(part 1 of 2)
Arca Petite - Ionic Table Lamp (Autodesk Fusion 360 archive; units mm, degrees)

design "Marble Base - Ionic Table Lamp - 120V" references "Trove - TL", "Balon v2", "Marble Base - Silicone Gasket", "Rubber Grommet", "Marble Base - Plastic Insert", "Chinois", "Neoprene Pad", "2-Pole Plug End", "Arca Tall", "T9 - Bulb", "Facet Petite", "T9-5In"
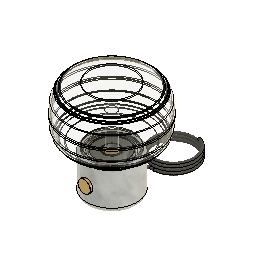
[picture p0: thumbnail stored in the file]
sketch "Sketch1" plane through (0, 0, 0) normal (0, 0, 1) x axis (1, 0, 0)
  circle C1 centre (0, 0) radius 63.5
  point P1 (0, 0)
  point P2 (0, 0)
  coincident P1 P2
extrude "Extrude1" new body sketch "Sketch1" along normal blind 101.6 bodies "Marble Base"
sketch "Sketch2" plane through (0, 0, 101.6) normal (0, 0, 1) x axis (-1, 0, 0)
  circle C1 centre (0, 0) radius 63.5
  circle C2 centre (0, 0) radius 53.975
  concentric C1 C2
  dimension "d3" diameter C2 = 107.95
extrude "Extrude2" cut sketch "Sketch2" profile of C2 against normal blind 34.925
sketch "Sketch3" plane through (0, 0, 66.675) normal (0, 0, 1) x axis (-1, 0, 0)
  circle C1 centre (0, 0) radius 53.975
  circle C2 centre (0, 0) radius 49.276
  point P1 (0, 0)
  point P3 (0, 0)
  coincident P1 P3
  dimension "d6" diameter C2 = 98.552
extrude "Extrude3" cut sketch "Sketch3" profile of C2 against normal blind 45.72
sketch "Sketch4" plane through (0, 0, 0) normal (0, 1, 0) x axis (1, 0, 0)
  circle C1 centre (0, -50.8) radius 3.81
  dimension "d9" diameter C1 = 7.62
extrude "Extrude4" cut sketch "Sketch4" against normal blind 127
sketch "Sketch5" plane through (0, 0, 0) normal (0, 1, 0) x axis (1, 0, 0)
  line L1 (0, -25.4) -> (0, 0)
  line L2 (0, -30.48) -> (0, -25.4)
  circle C1 centre (0, -30.48) radius 5.08
  point P1 (0, 0)
  point P2 (0, 0)
  point P4 (0, -30.48)
  point P5 (0, -30.48)
  coincident P1 P2
  vertical L1
  parallel L1 L2
  coincident P4 P5
  dimension "d12" diameter C1 = 10.16
extrude "Extrude5" cut sketch "Sketch5" profile of C1 along normal blind 114.3
fillet "Fillet1" radius 6.35 3.175 4.064
derived_base_feature "Derived Base Feature1" bodies "Rotary Switch"
derived_base_feature "Derived Base Feature1" bodies "Coiled - SVT (Blk Fabric)"
derived_base_feature "Derived Base Feature1" bodies "Glass Globe"
derived_base_feature "Derived Base Feature1" bodies "Metal Housing"
derived_base_feature "Derived Base Feature1" bodies "Metal Socket Cover"
derived_base_feature "Derived Base Feature1" bodies "Porcelain Socket"
derived_base_feature "Derived Base Feature1" bodies "Brass Dial - Dimmer Knob"
component_from_bodies "Body->Comp1"
offset_faces "OffsetFaces1" distance 12.7
offset_faces "OffsetFaces2" distance -12.7
derived_base_feature "Derived Base Feature1" bodies "Solitaire Petite"
move "Move1"
offset_faces "OffsetFaces1" distance 20.32
move "Move2"
extrude "Extrude6" add of existing geometry blind 25.4
offset_faces "OffsetFaces2" distance -3.81
fillet "Fillet2" radius 2.54
move "Move3"
derived_base_feature "Derived Base Feature2" bodies "Facet Petite"
move "Move4"
offset_faces "OffsetFaces1" distance 2.54
move "Move1"
derived_base_feature "Derived Base Feature1" bodies "Body1"
derived_base_feature "Derived Base Feature1" bodies "Body1"
derived_base_feature "Derived Base Feature1" bodies "Body1"
derived_base_feature "Derived Base Feature1" bodies "Body1"
derived_base_feature "Derived Base Feature1" bodies "Body1"
derived_base_feature "Derived Base Feature1" bodies "Body1", "Body2"
derived_base_feature "Derived Base Feature1" bodies "Body1"
position "Position1"
external_derived "ExternalDerived5" bodies "Plastic Insert"
derived_instance "DerivedInstance15"
offset_faces "OffsetFaces1" distance 3.81
offset_faces "OffsetFaces2" distance -1.0414
move "Move6"
external_derived "ExternalDerived6" sketch "Sketch3" bodies "Silicone Gasket"
derived_instance "DerivedInstance16"
offset_faces "OffsetFaces3" distance -10.795
move "Move1"
move_face "MoveFace1"
position "Position2"
position "Position3"
position "Position4"
position "Position5"
move "Move2"
position "Position6"
offset_faces "OffsetFaces2" distance -7.62
chamfer "Chamfer1" distance 0.381
remove_instance "RemoveInstance1"
remove_instance "RemoveInstance2"
remove_instance "RemoveInstance3"
remove_instance "RemoveInstance4"
move "Move1"
derived_base_feature "Derived Base Feature5" bodies "Oculo Petite"
align "Align1"
external_derived "ExternalDerived8"
derived_base_feature "Derived Base Feature7" bodies "Balon v2"
derived_base_feature "Derived Base Feature8" bodies "Balon v3"
align "Align3"
align "Align4"
external_derived "ExternalDerived10"
component_insert "Component Insert1"
position "Position7"
position "Position8"
derived_base_feature "Derived Base Feature11" bodies "Trove - TL"
move "Move10"
move "Move11"
remove_instance "RemoveInstance5"
split "Split1" bodies "Trove - TL (1)"
remove_body "RemoveBody2"
remove_body "RemoveBody3"
external_derived "ExternalDerived13" bodies "Trove - TL"
derived_instance "DerivedInstance20"
remove_body "RemoveBody4"
remove_body "RemoveBody5"
component_insert "Component Insert2"
component_insert "Component Insert3"
component_from_bodies "Body->Comp2"
remove_body "RemoveBody7"
move "Move12"
move "Move13"
sketch "Sketch6" plane through (0, 0, 97.917) normal (0, 0, 1) x axis (-1, 0, 0)
  circle C1 centre (0, 0) radius 41.275
  circle C2 centre (0, 0) radius 19.685
  arc A1 centre (0, 0) radius 29.3982 clockwise from (-27.6283, 10.0466) to (27.6283, 10.0466)
  arc A2 centre (0, 0) radius 26.2232 clockwise from (-24.6444, 8.9616) to (24.6444, 8.9616)
  arc A3 centre (0, 0) radius 32.5732 clockwise from (-30.6121, 11.1317) to (30.6121, 11.1317)
  arc A4 centre (0, 0) radius 35.7482 clockwise from (-33.596, 12.2167) to (33.596, 12.2167)
  point P1 (0, 0)
  point P3 (0, 0)
  coincident P1 P3
  dimension "d37" = -3.175
  dimension "d38" = 3.175
  dimension "d39" = 6.35
  dimension "d40" Text1-Height = 2.54
  dimension "d41" Text2-Height = 2.54
  dimension "d42" Text3-Height = 2.54
  dimension "d43" Text4-Height = 2.54
extrude "Extrude1" cut sketch "Sketch6" against normal blind 0.254
external_derived "ExternalDerived14" bodies "Rubber Grommet"
derived_instance "DerivedInstance19"
external_derived "ExternalDerived15" bodies "2-Pole Plug End"
derived_instance "DerivedInstance18"
external_derived "ExternalDerived16" bodies "Neoprene Pad"
derived_instance "DerivedInstance17"
position "Position9"
position "Position10"
position "Position11"
position "Position12"
external_derived "ExternalDerived17" bodies "Chinois"
derived_instance "DerivedInstance21"
position "Position13"
move "Move3"
remove_body "RemoveBody8"
component_insert "Component Insert4"
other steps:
derived_base_feature "Derived Base Feature1" bodies "Trove - TL"
derived_base_feature "Derived Base Feature1" bodies "Chinois"
derived_base_feature "Derived Base Feature1" bodies "Rubber Grommet"
derived_base_feature "Derived Base Feature1" bodies "2-Pole Plug End"
derived_base_feature "Derived Base Feature1" bodies "Neoprene Pad"
move "Move1"
base_feature "Base Feature1" bodies "Oculo Petite", "Arca Petite"
derived_base_feature "Derived Base Feature1" bodies "Plastic Insert"
derived_base_feature "Derived Base Feature1" bodies "Silicone Gasket"
base_feature "Base Feature1" bodies "Marble Base"
move "Move8"
derived_base_feature "Derived Base Feature"
create_component "CreateComponent1"
create_component "CreateComponent2"
create_component "CreateComponent3"
create_component "CreateComponent4"
create_component "CreateComponent5"
create_component "CreateComponent6"
create_component "CreateComponent7"
create_component "CreateComponent8"
remove_body "RemoveBody1"
create_component "CreateComponent9"
create_component "CreateComponent10"
create_component "CreateComponent11"
create_component "CreateComponent12"
create_component "CreateComponent13"
create_component "CreateComponent14"
create_component "CreateComponent15"
create_component "CreateComponent16"
create_component "CreateComponent17"
create_component "CreateComponent18"
remove_body "RemoveBody6"
create_component "CreateComponent19"
create_component "CreateComponent20"
create_component "CreateComponent21"
create_component "CreateComponent22"
create_component "CreateComponent23"
named bodies: "Marble Base", "Rotary Switch", "Coiled - SVT (Blk Fabric)", "Glass Globe", "Metal Housing", "Metal Socket Cover", "Porcelain Socket", "Brass Dial - Dimmer Knob", "Solitaire Petite", "Facet Petite", "Body1", "Body2", "Plastic Insert", "Silicone Gasket", "Oculo Petite", "Balon v2", "Balon v3", "Trove - TL", "Trove - TL (1)", "Arca Petite", "Neoprene Pad", "2-Pole Plug End", "Rubber Grommet", "Chinois"

design "Neoprene Pad"
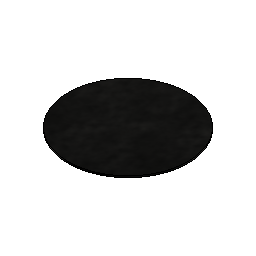
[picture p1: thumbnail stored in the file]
sketch "Sketch1" plane through (0, 0, 0) normal (0, 0, 1) x axis (1, 0, 0)
  circle C1 centre (0, 0) radius 57.15
  point P1 (0, 0)
  point P2 (0, 0)
  coincident P1 P2
extrude "Extrude1" new body sketch "Sketch1" along normal blind 1.5875 bodies "Neoprene Pad"
component_from_bodies "Body->Comp"
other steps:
base_feature "Base Feature" bodies "Neoprene Pad"
create_component "CreateComponent1"
remove_body "RemoveBody1"
named bodies: "Neoprene Pad"

design "T9 - Bulb"
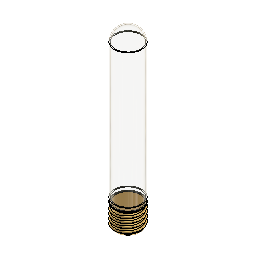
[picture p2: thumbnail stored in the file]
sketch "Sketch1" plane through (0, 0, 0) normal (0, 1, 0) x axis (1, 0, 0)
  line L1 (0, -166.37) -> (0, 0)
  line L2 (13.97, -13.97) -> (13.97, -152.4)
  line L3 (-13.97, -152.4) -> (-13.97, -13.97)
  line L4 (0, 0) -> (0, -166.37)
  line L5 (12.97, -13.97) -> (12.97, -152.4)
  line L6 (-12.97, -152.4) -> (-12.97, -13.97)
  line L7 (-12.3978, -10.16) -> (-13.4404, -10.16)
  line L8 (13.4404, -10.16) -> (12.3978, -10.16)
  arc A1 centre (0, -152.4) radius 13.97 clockwise from (13.97, -152.4) to (-13.97, -152.4)
  arc A2 centre (0, -152.4) radius 12.97 clockwise from (12.97, -152.4) to (-12.97, -152.4)
  arc A3 centre (0, -13.97) radius 13.97 clockwise from (13.4404, -10.16) to (13.97, -13.97)
  arc A4 centre (0, -13.97) radius 13.97 clockwise from (-13.97, -13.97) to (-13.4404, -10.16)
  arc A5 centre (0, -13.97) radius 12.97 clockwise from (12.3978, -10.16) to (12.97, -13.97)
  arc A6 centre (0, -13.97) radius 12.97 clockwise from (-12.97, -13.97) to (-12.3978, -10.16)
  point P1 (0, 0)
  point P2 (0, 0)
  point P3 (0, -166.37)
  point P10 (0, 0)
  point P17 (13.4404, -10.16)
  point P19 (12.3978, -10.16)
  point P4 (13.97, -152.4)
  point P5 (13.97, -13.97)
  coincident P1 P2
  vertical L1
  tangent L2 A3
  tangent L3 A3
  parallel L2 L3
  tangent L3 A1
  tangent L2 A1
  midpoint P3 A1
  coincident P1 P10
  perpendicular L1 L7
  coincident P17 L7
  concentric A3 A4
  coincident P10 A3
  concentric A1 A2
  tangent L5 A2
  tangent L5 A5
  tangent L6 A5
  tangent L6 A2
  coincident P19 L7
  concentric A5 A6
  collinear L7 L8
  dimension "d6" distance L2 L3 = 27.94
  dimension "d7" distance P4 P5 = 138.43
revolve "Revolve1" sketch "Sketch1" AlongAngle 360 bodies "T9"
derived_base_feature "Derived Base Feature" bodies "E26 Base"
align "Align1"
move "Move1"
component_from_bodies "Body->Comp1"
component_from_bodies "Body->Comp2"
copy_paste "CutPaste1"
copy_paste "CutPaste2"
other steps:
base_feature "Base Feature1" bodies "T9"
base_feature "Base Feature1" bodies "E26 Base"
create_component "CreateComponent1"
create_component "CreateComponent2"
remove_body "RemoveBody1"
create_component "CreateComponent3"
remove_body "RemoveBody2"
remove_instance "RemoveInstance1"
remove_instance "RemoveInstance2"
named bodies: "T9", "E26 Base"

design "Marble Base - Silicone Gasket"
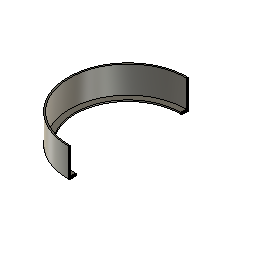
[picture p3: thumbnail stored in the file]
sketch "Sketch1" plane through (0, 0, 0) normal (0, 0, 1) x axis (1, 0, 0)
  circle C1 centre (0, 0) radius 53.34
  point P1 (0, 0)
  point P2 (0, 0)
  coincident P1 P2
extrude "Extrude1" new body sketch "Sketch1" along normal blind 25.4 bodies "Silicone Gasket"
shell "Shell1" innerThickness 1.27
sketch "Sketch2" plane through (0, 0, 1.27) normal (0, 0, 1) x axis (-1, 0, 0)
  circle C1 centre (0, 0) radius 52.07
  circle C2 centre (0, 0) radius 46.99
  concentric C1 C2
extrude "Extrude2" cut sketch "Sketch2" profile of C2 against normal blind 12.7
component_from_bodies "Body->Comp"
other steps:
base_feature "Base Feature" bodies "Silicone Gasket"
create_component "CreateComponent1"
remove_body "RemoveBody1"
named bodies: "Silicone Gasket"

design "2-Pole Plug End"
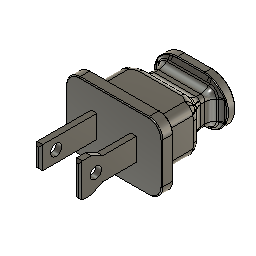
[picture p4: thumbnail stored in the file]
sketch "Sketch1" plane through (0, 0, 0) normal (0, 1, 0) x axis (1, 0, 0)
  line L1 (9.6837, 9.525) -> (-9.6837, 9.525)
  line L2 (13.4938, -5.715) -> (13.4938, 5.715)
  line L3 (-9.6837, -9.525) -> (9.6837, -9.525)
  line L4 (-13.4937, 5.715) -> (-13.4937, -5.715)
  line L5 (13.4938, -9.525) -> (-13.4937, 9.525)
  line L6 (-13.4937, -9.525) -> (13.4938, 9.525)
  arc A1 centre (-9.6837, -5.715) radius 3.81 clockwise from (-9.6837, -9.525) to (-13.4937, -5.715)
  arc A2 centre (9.6837, -5.715) radius 3.81 clockwise from (13.4938, -5.715) to (9.6837, -9.525)
  arc A3 centre (9.6837, 5.715) radius 3.81 clockwise from (9.6837, 9.525) to (13.4938, 5.715)
  arc A4 centre (-9.6837, 5.715) radius 3.81 clockwise from (-13.4937, 5.715) to (-9.6837, 9.525)
  point P6 (0, 0)
  point P1 (0, 0)
  point P5 (-13.4937, -9.525)
  point P4 (13.4938, -9.525)
  point P3 (13.4938, 9.525)
  point P2 (-13.4937, 9.525)
  horizontal L1
  perpendicular L1 L2
  parallel L1 L3
  parallel L2 L4
  coincident L5 P6
  coincident L6 P6
  coincident P1 P6
  coincident P5 L4
  coincident P5 L3
  tangent L4 A1
  tangent L3 A1
  coincident P4 L3
  coincident P4 L2
  tangent L3 A2
  tangent L2 A2
  equal A1 A2
  coincident P3 L2
  coincident P3 L1
  tangent L2 A3
  tangent L1 A3
  equal A1 A3
  coincident P2 L1
  coincident P2 L4
  tangent L1 A4
  tangent L4 A4
  equal A1 A4
  dimension "d1" distance P4 P5 = 26.9875
  dimension "d2" distance P2 P5 = 19.05
  dimension "d3" radius A1 = 3.81
extrude "Extrude1" new body sketch "Sketch1" profile of L1 L2 L3 L4 A1 A2 A3 A4 along normal blind 3.175
sketch "Sketch2" plane through (0, 3.175, 0) normal (0, 1, 0) x axis (-1, 0, 0)
  line L1 (9.6837, -9.525) -> (-9.6837, -9.525)
  line L2 (13.4937, 5.715) -> (13.4937, -5.715)
  line L3 (-9.6837, 9.525) -> (9.6837, 9.525)
  line L4 (-13.4938, -5.715) -> (-13.4938, 5.715)
  line L5 (10.16, -6.35) -> (-10.16, -6.35)
  line L6 (10.16, 6.35) -> (10.16, -6.35)
  line L7 (-10.16, 6.35) -> (10.16, 6.35)
  line L8 (-10.16, -6.35) -> (-10.16, 6.35)
  line L9 (10.16, 6.35) -> (-10.16, -6.35)
  line L10 (-10.16, 6.35) -> (10.16, -6.35)
  arc A1 centre (-9.6837, -5.715) radius 3.81 clockwise from (-9.6837, -9.525) to (-13.4938, -5.715)
  arc A2 centre (9.6837, -5.715) radius 3.81 clockwise from (13.4937, -5.715) to (9.6837, -9.525)
  arc A3 centre (9.6837, 5.715) radius 3.81 clockwise from (9.6837, 9.525) to (13.4937, 5.715)
  arc A4 centre (-9.6837, 5.715) radius 3.81 clockwise from (-13.4938, 5.715) to (-9.6837, 9.525)
  point P18 (0, 0)
  point P1 (0, 0)
  horizontal L5
  perpendicular L5 L6
  parallel L5 L7
  parallel L6 L8
  coincident L9 P18
  coincident L10 P18
  coincident P1 P18
extrude "Extrude2" add sketch "Sketch2" profile of L5 L6 L7 L8 along normal blind 9.525
sketch "Sketch3" plane through (0, 12.7, 0) normal (0, 1, 0) x axis (-1, 0, 0)
  line L1 (-10.16, -6.35) -> (-10.16, 6.35)
  line L2 (10.16, -6.35) -> (-10.16, -6.35)
  line L3 (10.16, 6.35) -> (10.16, -6.35)
  line L4 (-10.16, 6.35) -> (10.16, 6.35)
  line L5 (-7.1437, 3.9688) -> (7.1437, 3.9688)
  line L6 (-7.1437, -3.9688) -> (-7.1437, 3.9688)
  line L7 (7.1437, -3.9688) -> (-7.1437, -3.9688)
  line L8 (7.1437, 3.9688) -> (7.1437, -3.9688)
  line L9 (-7.1437, -3.9688) -> (7.1437, 3.9688)
  line L10 (7.1437, -3.9688) -> (-7.1437, 3.9688)
  point P10 (0, 0)
  point P1 (0, 0)
  point P8 (-7.1437, -3.9688)
  point P9 (7.1437, -3.9688)
  point P7 (-7.1437, 3.9688)
  horizontal L5
  perpendicular L5 L6
  parallel L5 L7
  parallel L6 L8
  coincident L9 P10
  coincident L10 P10
  coincident P1 P10
  dimension "d8" distance P8 P9 = 14.2875
  dimension "d9" distance P7 P8 = 7.9375
extrude "Extrude3" add sketch "Sketch3" profile of L5 L6 L7 L8 along normal blind 11.1125
fillet "Fillet1" radius 2.286 1.27 0.254
chamfer "Chamfer1" distance 3.429
fillet "Fillet2" radius 2.54 1.905
sketch "Sketch4" plane through (0, 23.8125, 0) normal (0, 1, 0) x axis (-1, 0, 0)
  line L1 (-7.1437, -2.6987) -> (-7.1437, 2.6987)
  line L2 (5.8737, -3.9688) -> (-5.8737, -3.9688)
  line L3 (7.1437, 2.6987) -> (7.1437, -2.6987)
  line L4 (-5.8737, 3.9688) -> (5.8737, 3.9688)
  line L5 (-3.81, 6.604) -> (3.81, 6.604)
  line L6 (3.81, -6.604) -> (-3.81, -6.604)
  line L7 (-10.414, 0) -> (10.414, 0)
  arc A1 centre (-5.8737, 2.6987) radius 1.27 clockwise from (-7.1437, 2.6987) to (-5.8737, 3.9688)
  arc A2 centre (-5.8737, -2.6987) radius 1.27 clockwise from (-5.8737, -3.9688) to (-7.1437, -2.6987)
  arc A3 centre (5.8737, -2.6987) radius 1.27 clockwise from (7.1437, -2.6987) to (5.8737, -3.9688)
  arc A4 centre (5.8737, 2.6987) radius 1.27 clockwise from (5.8737, 3.9688) to (7.1437, 2.6987)
  arc A5 centre (-3.81, 0) radius 6.604 clockwise from (-3.81, -6.604) to (-3.81, 6.604)
  arc A6 centre (3.81, 0) radius 6.604 clockwise from (3.81, 6.604) to (3.81, -6.604)
  point P20 (10.414, 0)
  point P21 (-10.414, 0)
  tangent L5 A5
  tangent A5 L6
  parallel L5 L6
  tangent L6 A6
  tangent L5 A6
  midpoint A6 P20
  midpoint A5 P21
  perpendicular L1 L7
extrude "Extrude4" add sketch "Sketch4" profile of A1 L1 A2 L2 A3 L3 A4 L4 L5 A5 L6 A6 against normal blind 2.286
chamfer "Chamfer2" distance 1.778
fillet "Fillet3" radius 1.778
fillet "Fillet4" radius 0.254
fillet "Fillet5" radius 0.254
fillet "Fillet6" radius 0.254
fillet "Fillet7" radius 3.175
sketch "Sketch5" plane through (0, 0, 0) normal (0, -1, 0) x axis (1, 0, 0)
  line L1 (-13.2397, -5.715) -> (-13.2397, 5.715)
  line L2 (9.6837, -9.271) -> (-9.6837, -9.271)
  line L3 (13.2397, 5.715) -> (13.2397, -5.715)
  line L4 (-9.6837, 9.271) -> (9.6837, 9.271)
  line L5 (-6.35, -3.175) -> (-6.35, 3.175)
  line L6 (6.35, 3.175) -> (-6.35, -3.175)
  line L7 (-6.35, 3.175) -> (6.35, -3.175)
  line L8 (-4.7625, 3.175) -> (-6.35, 3.175)
  line L9 (-4.7625, -3.175) -> (-4.7625, 3.175)
  line L10 (-6.35, -3.175) -> (-4.7625, -3.175)
  line L11 (-6.35, 3.175) -> (-6.35, -3.175)
  line L12 (0, -3.302) -> (0, 3.81)
  line L13 (4.7625, -3.175) -> (4.7625, 3.175)
  line L14 (4.7625, 3.175) -> (6.35, 3.175)
  line L15 (6.35, -3.175) -> (6.35, 3.175)
  line L16 (6.35, -3.175) -> (4.7625, -3.175)
  arc A1 centre (-9.6837, 5.715) radius 3.556 clockwise from (-13.2397, 5.715) to (-9.6837, 9.271)
  arc A2 centre (-9.6837, -5.715) radius 3.556 clockwise from (-9.6837, -9.271) to (-13.2397, -5.715)
  arc A3 centre (9.6837, -5.715) radius 3.556 clockwise from (13.2397, -5.715) to (9.6837, -9.271)
  arc A4 centre (9.6837, 5.715) radius 3.556 clockwise from (9.6837, 9.271) to (13.2397, 5.715)
  point P18 (0, 0)
  point P1 (0, 0)
  point P14 (-6.35, -3.175)
  point P27 (6.35, -3.175)
  point P17 (-6.35, 3.175)
  point P26 (6.35, 3.175)
  point P19 (-4.7625, 3.175)
  point P24 (4.7625, 3.175)
  point P20 (-4.7625, -3.175)
  point P25 (4.7625, -3.175)
  point P21 (-6.35, -3.175)
  point P28 (6.35, -3.175)
  point P15 (6.35, -3.175)
  point P16 (6.35, 3.175)
  coincident L6 P18
  coincident L7 P18
  coincident P1 P18
  horizontal L8
  vertical L9
  horizontal L10
  vertical L11
  vertical L12
  symmetric P14 L12 P27
  symmetric P17 L12 P26
  symmetric P19 L12 P24
  symmetric P20 L12 P25
  symmetric P21 L12 P28
  dimension "d36" distance P15 P16 = 6.35
  dimension "d37" distance P17 P19 = 1.5875
extrude "Extrude5" add sketch "Sketch5" profile of L5 L8 L9 L10 L11 L13 L14 L15 L16 along normal blind 15.875
sketch "Sketch7" plane through (0, 0, 3.175) normal (0, 0, 1) x axis (-1, 0, 0)
  line L1 (-4.7625, 0) -> (-6.35, 0)
  line L2 (-4.7625, 15.875) -> (-4.7625, 0)
  line L3 (-6.35, 15.875) -> (-4.7625, 15.875)
  line L4 (-6.35, 0) -> (-6.35, 15.875)
  line L5 (-4.7625, 15.875) -> (-6.35, 15.875)
  line L6 (-4.7625, 9.525) -> (-4.7625, 15.875)
  line L7 (-6.35, 9.525) -> (-4.7625, 9.525)
  line L8 (-6.35, 15.875) -> (-6.35, 9.525)
  point P5 (-6.35, 15.875)
  point P6 (-6.35, 15.875)
  point P9 (-6.35, 9.525)
  horizontal L5
  vertical L6
  horizontal L7
  vertical L8
  coincident P5 P6
  dimension "d45" distance P6 P9 = 6.35
extrude "Extrude7" add sketch "Sketch7" profile of L2 L3 L4 L5 L6 L7 L8 against normal blind 7.9375 and along normal blind 1.5875
chamfer "Chamfer3" distance 0.508
chamfer "Chamfer4" distance 0.635 distance 0.635
sketch "Sketch6" plane through (6.35, 0, 0) normal (1, 0, 0) x axis (0, 1, 0)
  line L1 (0, -3.175) -> (-9.525, -3.175)
  line L2 (0, 3.175) -> (0, -3.175)
  line L3 (-9.525, 3.175) -> (0, 3.175)
  line L4 (-15.367, -4.6355) -> (-15.367, 4.6355)
  line L5 (-11.43, 0) -> (-16.002, 0)
  line L6 (-9.525, -4.7625) -> (-15.24, -4.7625)
  line L7 (-9.525, -3.175) -> (-9.525, -4.7625)
  line L8 (-9.525, 4.7625) -> (-9.525, 3.175)
  line L9 (-15.24, 4.7625) -> (-9.525, 4.7625)
  line L10 (-15.24, -4.7625) -> (-15.367, -4.6355)
  line L11 (-15.367, 4.6355) -> (-15.24, 4.7625)
  circle C1 centre (-11.43, 0) radius 1.5875
  point P9 (-11.43, 0)
  point P10 (-11.43, 0)
  perpendicular L4 L5
  coincident P9 P10
  dimension "d42" diameter C1 = 3.175
extrude "Extrude6" cut sketch "Sketch6" profile of C1 against normal blind 20.32
chamfer "Chamfer5" distance 3.175 distance 1.5875 distance 3.175 distance 1.5875
component_from_bodies "Body->Comp"
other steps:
base_feature "Base Feature" bodies "2-Pole Plug End"
create_component "CreateComponent1"
remove_body "RemoveBody1"
named bodies: "2-Pole Plug End"

design "Facet Petite"
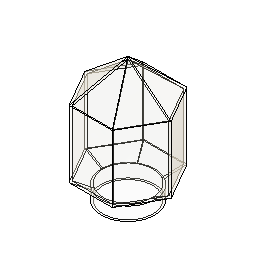
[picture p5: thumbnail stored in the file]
sketch "Sketch7" plane through (0, 0, 0) normal (1, 0, 0) x axis (0, 1, 0)
sketch "Sketch8" plane through (0, 0, 0) normal (0, 0, 1) x axis (1, 0, 0)
  circle C1 centre (0, 0) radius 50.8
  point P1 (0, 0)
  point P2 (0, 0)
  coincident P1 P2
  dimension "d17" diameter C1 = 101.6
extrude "Extrude5" new body sketch "Sketch8" along normal blind 25.4 and against normal blind 25.4
work_plane "WorkPlane1" AlongDistance 17.78
sketch "Sketch10" plane through (0, 0, 25.4) normal (0, 0, 1) x axis (-1, 0, 0)
  circle C1 centre (0, 0) radius 50.8
sketch "Sketch12" plane through (0, 0, 43.18) normal (0, 0, 1) x axis (1, 0, 0)
  line L1 (-82.1223, 0) -> (-41.0612, 71.12)
  line L2 (-41.0612, -71.12) -> (-82.1223, 0)
  line L3 (41.0612, -71.12) -> (-41.0612, -71.12)
  line L4 (82.1223, 0) -> (41.0612, -71.12)
  line L5 (41.0612, 71.12) -> (82.1223, 0)
  line L6 (-41.0612, 71.12) -> (41.0612, 71.12)
  point P1 (0, 0)
  point P8 (0, 0)
  coincident P1 P8
  dimension "d22" distance P8 L6 = 71.12
sketch "Sketch15" plane through (0, 0, 0) normal (0, 1, 0) x axis (1, 0, 0)
  line L1 (53.7365, -21.6801) -> (82.1223, -43.18)
  line L2 (-50.8, -25.4) -> (-82.1223, -43.18)
  point P2 (82.1223, -43.18)
  point P3 (82.1223, -43.18)
  point P5 (-82.1223, -43.18)
  point P7 (-82.1223, -43.18)
  point P6 (-50.8, -25.4)
  point P8 (-50.8, -25.4)
  coincident P2 P3
  coincident P5 P7
  coincident P6 P8
sketch "Sketch17" plane through (0, 0, 25.4) normal (0, 0, 1) x axis (-1, 0, 0)
  line L1 (51.3255, 0) -> (0, 0)
  line L2 (73.3235, 0) -> (0, 0)
  line L3 (-41.0612, -71.12) -> (-25.4, -43.9941)
  line L4 (-36.6617, -63.5) -> (-25.4, -43.9941)
  line L5 (78.4305, 0) -> (0, 0)
  line L6 (41.0612, -71.12) -> (25.4, -43.9941)
  line L7 (25.4, 43.9941) -> (41.0612, 71.12)
  line L8 (73.3235, 0) -> (0, 0)
  line L9 (-25.4, 43.9941) -> (-41.0612, 71.12)
  line L10 (0, 0) -> (0, 0)
  circle C1 centre (0, 0) radius 50.8
  point P1 (0, 0)
  point P4 (0, 0)
  point P2 (-41.0612, -71.12)
  point P6 (-41.0612, -71.12)
  point P3 (0, 0)
  point P7 (0, 0)
  point P9 (-25.4, -43.9941)
  point P12 (41.0612, -71.12)
  point P13 (41.0612, -71.12)
  point P15 (25.4, -43.9941)
  point P16 (41.0612, 71.12)
  point P17 (41.0612, 71.12)
  point P18 (25.4, 43.9941)
  point P19 (-41.0612, 71.12)
  point P20 (-41.0612, 71.12)
  point P21 (0, 0)
  point P23 (-25.4, 43.9941)
  point P25 (0, 0)
  point P24 (0, 0)
  point P26 (0, 0)
  horizontal L1
  coincident P1 P4
  coincident P2 P6
  horizontal L2
  coincident P3 P7
  coincident C1 P9
  coincident P12 P13
  horizontal L5
  coincident C1 P15
  coincident P16 P17
  coincident C1 P18
  coincident P19 P20
  horizontal L8
  coincident P1 P21
  coincident C1 P23
  coincident P1 P25
  coincident P24 P26
extrude "Extrude6" new body sketch "Sketch12" along normal blind 127
work_plane "WorkPlane2" AlongDistance 66.04
sketch "Sketch18" plane through (0, 0, 236.22) normal (0, 0, 1) x axis (1, 0, 0)
  line L1 (41.0612, -71.12) -> (0, 0)
  line L2 (82.1223, 0) -> (0, 0)
  line L3 (41.0612, 71.12) -> (0, 0)
  line L4 (-41.0612, 71.12) -> (0, 0)
  line L5 (-82.1223, 0) -> (0, 0)
  line L6 (-41.0612, -71.12) -> (0, 0)
  point P1 (0, 0)
  point P3 (0, 0)
  point P2 (41.0612, -71.12)
  point P4 (41.0612, -71.12)
  point P6 (0, 0)
  point P5 (82.1223, 0)
  point P7 (82.1223, 0)
  point P9 (0, 0)
  point P8 (41.0612, 71.12)
  point P10 (41.0612, 71.12)
  point P12 (0, 0)
  point P11 (-41.0612, 71.12)
  point P13 (-41.0612, 71.12)
  point P15 (0, 0)
  point P14 (-82.1223, 0)
  point P16 (-82.1223, 0)
  point P18 (0, 0)
  point P17 (-41.0612, -71.12)
  point P19 (-41.0612, -71.12)
  coincident P1 P3
  coincident P2 P4
  coincident P1 P6
  coincident P5 P7
  coincident P1 P9
  coincident P8 P10
  coincident P1 P12
  coincident P11 P13
  coincident P1 P15
  coincident P14 P16
  coincident P1 P18
  coincident P17 P19
loft "Loft1"
loft "Loft2" sketch "Sketch17"
component_from_bodies "Body->Comp"
extrude "Extrude1" cut of existing geometry blind -25.4
shell "Shell2" innerThickness 3.81
fillet "Fillet1" radius 7.62
fillet "Fillet2" radius 6.35
fillet "Fillet3" radius 6.35
fillet "Fillet4" radius 6.35
fillet "Fillet5" radius 6.35
fillet "Fillet6" radius 6.35
fillet "Fillet7" radius 3.81
fillet "Fillet8" radius 6.35
fillet "Fillet9" radius 6.35
fillet "Fillet10" radius 6.35
fillet "Fillet11" radius 6.35
fillet "Fillet12" radius 6.35
fillet "Fillet13" radius 2.286
shell "Shell1" innerThickness 2.54
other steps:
base_feature "Base Feature"
create_component "CreateComponent3"
remove_body "RemoveBody2"

design "Chinois"
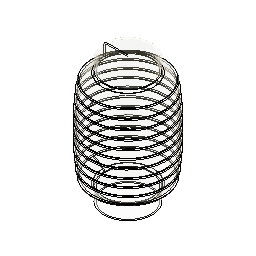
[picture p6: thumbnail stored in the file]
named bodies: "Chinois"

design "Marble Base - Plastic Insert"
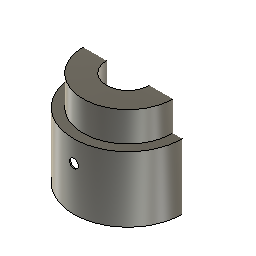
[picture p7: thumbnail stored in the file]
sketch "Sketch1" plane through (0, 0, 0) normal (0, 0, 1) x axis (1, 0, 0)
  circle C1 centre (0, 0) radius 50.038
  point P1 (0, 0)
  point P2 (0, 0)
  coincident P1 P2
  dimension "d1" diameter C1 = 100.076
extrude "Extrude1" new body sketch "Sketch1" along normal blind 72.898 bodies "Plastic Insert"
shell "Shell1" innerThickness 1.016
work_plane "WorkPlane1" AlongDistance 18.034
sketch "Sketch2" plane through (0, 0, 90.932) normal (0, 0, 1) x axis (1, 0, 0)
  circle C1 centre (0, 0) radius 20.701
  point P1 (0, 0)
  point P2 (0, 0)
  coincident P1 P2
  dimension "d6" diameter C1 = 41.402
extrude "Extrude2" add sketch "Sketch2" against normal blind 65.024
shell "Shell2" innerThickness 1.016
sketch "Sketch3" plane through (0, 0, 0) normal (0, 1, 0) x axis (1, 0, 0)
  line L1 (5.08, -20.32) -> (-5.08, -20.32)
  line L2 (5.08, 20.32) -> (5.08, -20.32)
  line L3 (-5.08, 20.32) -> (5.08, 20.32)
  line L4 (-5.08, -20.32) -> (-5.08, 20.32)
  line L5 (5.08, 20.32) -> (-5.08, -20.32)
  line L6 (-5.08, 20.32) -> (5.08, -20.32)
  point P6 (0, 0)
  point P1 (0, 0)
  horizontal L1
  perpendicular L1 L2
  parallel L1 L3
  parallel L2 L4
  coincident L5 P6
  coincident L6 P6
  coincident P1 P6
extrude "Extrude3" cut sketch "Sketch3" profile of L1 L2 L3 L4 along normal blind 91.44
sketch "Sketch4" plane through (0, 0, 0) normal (0, 1, 0) x axis (1, 0, 0)
  line L1 (0, -40.64) -> (0, 0)
  circle C1 centre (0, -40.64) radius 4.064
  point P1 (0, 0)
  point P2 (0, 0)
  point P3 (0, -40.64)
  point P4 (0, -40.64)
  coincident P1 P2
  vertical L1
  coincident P3 P4
  dimension "d12" diameter C1 = 8.128
work_plane "WorkPlane2" AlongDistance -91.44
sketch "Sketch5" plane through (0, -91.44, 0) normal (0, 1, 0) x axis (1, 0, 0)
  circle C1 centre (0, -40.64) radius 4.064
extrude "Extrude4" cut sketch "Sketch5" along normal blind 63.5
sketch "Sketch6" plane through (0, 0, 26.924) normal (0, 0, 1) x axis (-1, 0, 0)
  circle C1 centre (0, 0) radius 19.685
  circle C2 centre (0, 0) radius 5.461
  concentric C1 C2
  dimension "d16" diameter C2 = 10.922
extrude "Extrude5" cut sketch "Sketch6" profile of C2 against normal blind 15.24
sketch "Sketch7" plane through (0, 0, 72.898) normal (0, 0, 1) x axis (-1, 0, 0)
  circle C1 centre (0, 0) radius 20.701
  circle C2 centre (0, 0) radius 50.038
  circle C3 centre (0, 0) radius 20.701
  circle C4 centre (0, 0) radius 45.72
  point P1 (0, 0)
  point P3 (0, 0)
  point P4 (0, 0)
  coincident P1 P3
  coincident P1 P4
extrude "Extrude6" add sketch "Sketch7" profile of C1 C3 C4 along normal blind 18.034
sketch "Sketch8" plane through (0, 0, 71.882) normal (0, 0, -1) x axis (1, 0, 0)
  circle C1 centre (0, 0) radius 20.701
  circle C2 centre (0, 0) radius 49.022
  circle C3 centre (0, 0) radius 20.701
  circle C4 centre (0, 0) radius 44.704
  point P1 (0, 0)
  point P3 (0, 0)
  point P4 (0, 0)
  coincident P1 P3
  coincident P1 P4
  dimension "d21" diameter C4 = 89.408
extrude "Extrude7" cut sketch "Sketch8" profile of C1 C3 C4 against normal blind 17.78
extrude "Extrude8" add of existing geometry blind 9.398
extrude "Extrude9" cut of existing geometry blind -9.398
component_from_bodies "Body->Comp"
offset_faces "OffsetFaces1" distance 4.445
offset_faces "OffsetFaces2" distance -4.445
offset_faces "OffsetFaces3" distance 3.175
offset_faces "OffsetFaces4" distance 3.175
offset_faces "OffsetFaces5" distance 3.175
offset_faces "OffsetFaces6" distance -3.175
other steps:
base_feature "Base Feature" bodies "Plastic Insert"
create_component "CreateComponent1"
remove_body "RemoveBody1"
named bodies: "Plastic Insert"

design "Arca Tall"
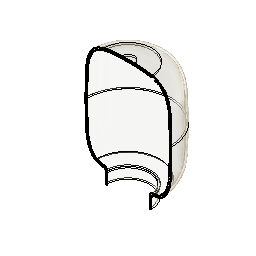
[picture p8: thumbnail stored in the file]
derived_base_feature "Derived Base Feature" bodies "Balon"
work_plane "WorkPlane1" AlongDistance 0
sketch "Sketch1" plane through (0, 0, 0) normal (0, 1, 0) x axis (1, 0, 0)
  line L1 (0, 317.5) -> (0, 2.9083)
  curve K1 (-82.9821, 124.2212) -> (-50.8, 237.8015)
  curve K2 (-51.0925, 237.681) -> (-50.8, 237.8015)
  curve K3 (-51.3855, 237.5558) -> (-51.0925, 237.681)
  curve K4 (-54.7608, 236.0513) -> (-51.3855, 237.5558)
  curve K5 (-57.9615, 234.05) -> (-54.7608, 236.0513)
  curve K6 (-67.2727, 226.749) -> (-57.9615, 234.05)
  curve K7 (-69.0552, 224.2615) -> (-67.2727, 226.749)
  curve K8 (-72.1872, 218.7832) -> (-69.0552, 224.2615)
  curve K9 (-74.1213, 215.1556) -> (-72.1872, 218.7832)
  curve K10 (-78.3031, 204.3965) -> (-74.1213, 215.1556)
  curve K11 (-79.7275, 197.3397) -> (-78.3031, 204.3965)
  curve K12 (-81.3333, 185.4664) -> (-79.7275, 197.3397)
  curve K13 (-81.6254, 178.4008) -> (-81.3333, 185.4664)
  curve K14 (-82.49, 152.2133) -> (-81.6254, 178.4008)
  curve K15 (-82.9821, 136.067) -> (-82.49, 152.2133)
  curve K16 (-82.9821, 124.2212) -> (-82.9821, 136.067)
  curve K17 (50.8, 237.7999) -> (82.9821, 124.2212)
  curve K18 (82.9821, 140.3031) -> (82.9821, 124.2212)
  curve K19 (81.9353, 169.4257) -> (82.9821, 140.3031)
  curve K20 (81.3621, 183.6489) -> (81.9353, 169.4257)
  curve K21 (80.9478, 189.8724) -> (81.3621, 183.6489)
  curve K22 (77.8147, 206.9858) -> (80.9478, 189.8724)
  curve K23 (74.9652, 213.2153) -> (77.8147, 206.9858)
  curve K24 (69.4688, 224.1531) -> (74.9652, 213.2153)
  curve K25 (67.2512, 226.458) -> (69.4688, 224.1531)
  curve K26 (61.5696, 231.3138) -> (67.2512, 226.458)
  curve K27 (57.377, 234.6711) -> (61.5696, 231.3138)
  curve K28 (52.0556, 237.2628) -> (57.377, 234.6711)
  curve K29 (51.4313, 237.5413) -> (52.0556, 237.2628)
  curve K30 (50.8, 237.7999) -> (51.4313, 237.5413)
  line L2 (-50.8, 317.5) -> (-50.8, 237.8015)
  line L3 (50.8, 317.5) -> (50.8, 237.7999)
  line L4 (-19.0713, 6.7501) -> (-19.0713, 6.7501)
  curve K31 (82.9821, 124.1958) -> (40.1509, 7.3012)
  curve K32 (41.8198, 7.6176) -> (40.1509, 7.3012)
  curve K33 (43.2113, 8.0663) -> (41.8198, 7.6176)
  curve K34 (47.0139, 9.2854) -> (43.2113, 8.0663)
  curve K35 (47.3314, 9.3805) -> (47.0139, 9.2854)
  curve K36 (50.1192, 10.3272) -> (47.3314, 9.3805)
  curve K37 (51.833, 11.0085) -> (50.1192, 10.3272)
  curve K38 (57.8313, 14.1895) -> (51.833, 11.0085)
  curve K39 (61.4491, 17.0488) -> (57.8313, 14.1895)
  curve K40 (66.8203, 21.5867) -> (61.4491, 17.0488)
  curve K41 (68.5372, 23.5528) -> (66.8203, 21.5867)
  curve K42 (71.2201, 27.8971) -> (68.5372, 23.5528)
  curve K43 (74.7424, 33.8984) -> (71.2201, 27.8971)
  curve K44 (78.2342, 44.8406) -> (74.7424, 33.8984)
  curve K45 (79.6792, 50.3463) -> (78.2342, 44.8406)
  curve K46 (81.3558, 63.5576) -> (79.6792, 50.3463)
  curve K47 (81.6386, 70.4415) -> (81.3558, 63.5576)
  curve K48 (82.4897, 96.2198) -> (81.6386, 70.4415)
  curve K49 (82.9814, 112.3523) -> (82.4897, 96.2198)
  curve K50 (82.9821, 124.1958) -> (82.9814, 112.3523)
  curve K51 (-40.1501, 7.301) -> (-82.9821, 124.1958)
  curve K52 (-82.9813, 110.5256) -> (-82.9821, 124.1958)
  curve K53 (-82.2545, 88.8594) -> (-82.9813, 110.5256)
  curve K54 (-81.6277, 70.519) -> (-82.2545, 88.8594)
  curve K55 (-81.3572, 64.3441) -> (-81.6277, 70.519)
  curve K56 (-79.4149, 46.8924) -> (-81.3572, 64.3441)
  curve K57 (-76.5204, 38.9768) -> (-79.4149, 46.8924)
  curve K58 (-73.5142, 32.2947) -> (-76.5204, 38.9768)
  curve K59 (-72.5556, 30.3818) -> (-73.5142, 32.2947)
  curve K60 (-69.7914, 25.3691) -> (-72.5556, 30.3818)
  curve K61 (-68.3824, 23.4028) -> (-69.7914, 25.3691)
  curve K62 (-64.5419, 19.5456) -> (-68.3824, 23.4028)
  curve K63 (-62.3002, 17.7646) -> (-64.5419, 19.5456)
  curve K64 (-53.6583, 11.1976) -> (-62.3002, 17.7646)
  curve K65 (-49.6968, 10.1396) -> (-53.6583, 11.1976)
  curve K66 (-43.4141, 8.1331) -> (-49.6968, 10.1396)
  curve K67 (-41.9704, 7.6516) -> (-43.4141, 8.1331)
  curve K68 (-40.1963, 7.3098) -> (-41.9704, 7.6516)
  curve K69 (-40.1732, 7.3054) -> (-40.1963, 7.3098)
  curve K70 (-40.1501, 7.301) -> (-40.1732, 7.3054)
  line L5 (-82.9821, 124.1958) -> (-82.9821, 124.2212)
  line L6 (82.9821, 124.2212) -> (82.9821, 124.1958)
  line L7 (0, 317.5) -> (-50.8, 317.5)
  line L8 (7.2015, 3.048) -> (0, 3.048)
  line L9 (0, 3.048) -> (-7.2015, 3.048)
  arc A1 centre (0, 188.595) radius 185.6867 clockwise from (-7.2015, 3.048) to (-40.1502, 7.301)
  arc A2 centre (0, 188.595) radius 185.6867 clockwise from (40.151, 7.3012) to (7.2015, 3.048)
  point P38 (-40.1502, 7.301)
  point P43 (40.1509, 7.3012)
  point P62 (-40.1501, 7.301)
  point P81 (40.151, 7.3012)
  point P84 (0, 3.048)
  vertical L1
  horizontal L4
  coincident P38 K51
  symmetric L1 A1 A2
  coincident A2 P43
  coincident A1 P62
  coincident K31 P81
  perpendicular L2 L7
  horizontal L8
  coincident L1 P84
  horizontal L9
revolve "Revolve1" sketch "Sketch1" AlongAngle 360
shell "Shell1" innerThickness 3.81
fillet "Fillet1" radius 6.35 bodies "Balon v3"
offset_faces "OffsetFaces1" distance -50.8
move "Move1"
move "Move2"
component_from_bodies "Body->Comp1"
component_from_bodies "Body->Comp2"
sketch "Sketch2" plane through (0, 0, 0) normal (0, 1, 0) x axis (1, 0, 0)
  line L1 (-85.5221, 124.2212) -> (-85.5221, 124.1961)
  curve K1 (-58.9057, 236.4383) -> (-50.8, 241.7989)
  curve K2 (-50.8, 241.554) -> (-50.8, 241.7989)
  curve K3 (-50.904, 240.933) -> (-50.8, 241.554)
  curve K4 (-51.2936, 240.2837) -> (-50.904, 240.933)
  curve K5 (-51.734, 239.7561) -> (-51.2936, 240.2837)
  curve K6 (-53.328, 238.5038) -> (-51.734, 239.7561)
  curve K7 (-54.0892, 238.1997) -> (-53.328, 238.5038)
  curve K8 (-58.9057, 236.4383) -> (-54.0892, 238.1997)
  curve K9 (-89.3309, 124.2212) -> (-58.9057, 236.4383)
  curve K10 (-62.6336, 234.9735) -> (-58.9057, 236.4383)
  curve K11 (-65.581, 233.1032) -> (-62.6336, 234.9735)
  curve K12 (-73.0224, 227.0019) -> (-65.581, 233.1032)
  curve K13 (-74.8981, 224.836) -> (-73.0224, 227.0019)
  curve K14 (-78.1104, 219.6097) -> (-74.8981, 224.836)
  curve K15 (-80.2663, 215.561) -> (-78.1104, 219.6097)
  curve K16 (-84.0943, 205.8277) -> (-80.2663, 215.561)
  curve K17 (-85.4655, 200.1154) -> (-84.0943, 205.8277)
  curve K18 (-87.4092, 188.5789) -> (-85.4655, 200.1154)
  curve K19 (-87.7349, 182.3889) -> (-87.4092, 188.5789)
  curve K20 (-88.4233, 165.9645) -> (-87.7349, 182.3889)
  curve K21 (-89.328, 138.6964) -> (-88.4233, 165.9645)
  curve K22 (-89.3309, 124.2212) -> (-89.328, 138.6964)
  line L2 (-89.3309, 124.1958) -> (-89.3309, 124.2212)
  curve K23 (-46.5001, 7.301) -> (-89.3309, 124.1958)
  curve K24 (-89.3314, 112.4293) -> (-89.3309, 124.1958)
  curve K25 (-88.8181, 95.3068) -> (-89.3314, 112.4293)
  curve K26 (-88.346, 81.2892) -> (-88.8181, 95.3068)
  curve K27 (-88.0298, 70.4902) -> (-88.346, 81.2892)
  curve K28 (-87.1514, 58.328) -> (-88.0298, 70.4902)
  curve K29 (-86.3326, 50.6119) -> (-87.1514, 58.328)
  curve K30 (-81.0932, 33.6688) -> (-86.3326, 50.6119)
  curve K31 (-77.3163, 27.4309) -> (-81.0932, 33.6688)
  curve K32 (-74.8955, 23.6666) -> (-77.3163, 27.4309)
  curve K33 (-73.5108, 22.0741) -> (-74.8955, 23.6666)
  curve K34 (-70.2346, 19.0457) -> (-73.5108, 22.0741)
  curve K35 (-64.8094, 14.3548) -> (-70.2346, 19.0457)
  curve K36 (-56.6696, 10.3041) -> (-64.8094, 14.3548)
  curve K37 (-54.0053, 9.483) -> (-56.6696, 10.3041)
  curve K38 (-49.1487, 7.9411) -> (-54.0053, 9.483)
  curve K39 (-48.3482, 7.6526) -> (-49.1487, 7.9411)
  curve K40 (-46.5001, 7.301) -> (-48.3482, 7.6526)
  line L3 (0, 266.7) -> (0, 0)
  line L4 (0, 3.048) -> (-7.7894, 3.048)
  line L5 (-50.8, 266.7) -> (-50.8, 241.7989)
  line L6 (0, 266.7) -> (-50.8, 266.7)
  arc A1 centre (-6.9779, 188.7329) radius 185.6867 clockwise from (-7.7894, 3.048) to (-46.5001, 7.301)
  point P1 (0, 0)
  point P44 (0, 0)
  point P46 (0, 3.048)
  point P5 (-50.8, 241.554)
  point P49 (0, 266.7)
  coincident P1 P44
  coincident L3 P46
  coincident P5 L5
  coincident L3 P49
revolve "Revolve2" sketch "Sketch2" AlongAngle 360 bodies "Balon v3"
shell "Shell2" innerThickness 3.81
component_from_bodies "Body->Comp3"
remove_instance "RemoveInstance1"
remove_instance "RemoveInstance2"
sketch "Sketch1" plane through (0, 0, 0) normal (0, 1, 0) x axis (1, 0, 0)
  line L1 (-6.35, 3.048) -> (-14.1394, 3.048)
  curve K1 (-52.8501, 7.301) -> (-95.6809, 124.1958)
  curve K2 (-95.6814, 112.4293) -> (-95.6809, 124.1958)
  curve K3 (-95.1681, 95.3068) -> (-95.6814, 112.4293)
  curve K4 (-94.696, 81.2892) -> (-95.1681, 95.3068)
  curve K5 (-94.3798, 70.4902) -> (-94.696, 81.2892)
  curve K6 (-93.5014, 58.328) -> (-94.3798, 70.4902)
  curve K7 (-92.6826, 50.6119) -> (-93.5014, 58.328)
  curve K8 (-87.4432, 33.6688) -> (-92.6826, 50.6119)
  curve K9 (-83.6663, 27.4309) -> (-87.4432, 33.6688)
  curve K10 (-81.2455, 23.6666) -> (-83.6663, 27.4309)
  curve K11 (-79.8608, 22.0741) -> (-81.2455, 23.6666)
  curve K12 (-76.5846, 19.0457) -> (-79.8608, 22.0741)
  curve K13 (-71.12, 13.97) -> (-76.5846, 19.0457)
  curve K14 (-62.23, 10.16) -> (-71.12, 13.97)
  curve K15 (-60.3553, 9.483) -> (-62.23, 10.16)
  curve K16 (-55.4987, 7.9411) -> (-60.3553, 9.483)
  curve K17 (-54.6982, 7.6526) -> (-55.4987, 7.9411)
  curve K18 (-52.8501, 7.301) -> (-54.6982, 7.6526)
  line L2 (-95.6809, 124.1958) -> (-95.6809, 124.2212)
  line L3 (0, 266.7) -> (0, 0)
  line L4 (0, 3.048) -> (-6.35, 3.048)
  line L5 (-95.6809, 124.2466) -> (-95.6809, 124.2212)
  line L6 (-50.8, 266.7) -> (-50.8, 241.7989)
  line L7 (0, 266.7) -> (-50.8, 266.7)
  curve K19 (-71.6837, 232.5587) -> (-50.8, 241.7989)
  curve K20 (-50.8, 237.8015) -> (-50.8, 241.7989)
  curve K21 (-53.6019, 236.5654) -> (-50.8, 237.8015)
  curve K22 (-59.7861, 236.0598) -> (-53.6019, 236.5654)
  curve K23 (-64.4375, 235.2772) -> (-59.7861, 236.0598)
  curve K24 (-69.8917, 233.4707) -> (-64.4375, 235.2772)
  curve K25 (-71.6837, 232.5587) -> (-69.8917, 233.4707)
  curve K26 (-71.6837, 232.5587) -> (-95.6809, 124.2466)
  curve K27 (-95.6814, 136.0132) -> (-95.6809, 124.2466)
  curve K28 (-95.1681, 153.1357) -> (-95.6814, 136.0132)
  curve K29 (-94.696, 167.1533) -> (-95.1681, 153.1357)
  curve K30 (-94.3798, 177.9523) -> (-94.696, 167.1533)
  curve K31 (-93.5014, 190.1145) -> (-94.3798, 177.9523)
  curve K32 (-92.6826, 197.8306) -> (-93.5014, 190.1145)
  curve K33 (-87.4432, 214.7737) -> (-92.6826, 197.8306)
  curve K34 (-83.6663, 221.0115) -> (-87.4432, 214.7737)
  curve K35 (-81.2455, 224.7759) -> (-83.6663, 221.0115)
  curve K36 (-79.8608, 226.3684) -> (-81.2455, 224.7759)
  curve K37 (-77.083, 228.9361) -> (-79.8608, 226.3684)
  curve K38 (-75.5537, 230.2778) -> (-77.083, 228.9361)
  curve K39 (-71.6837, 232.5587) -> (-75.5537, 230.2778)
  curve K40 (-50.8, 244.8458) -> (-50.8, 244.8469)
  curve K41 (-50.8, 244.8465) -> (-50.8, 244.8469)
  curve K42 (-50.8, 244.8462) -> (-50.8, 244.8465)
  curve K43 (-50.8, 244.8458) -> (-50.8, 244.8462)
  arc A1 centre (-13.3279, 188.7329) radius 185.6867 clockwise from (-14.1394, 3.048) to (-52.8501, 7.301)
  point P26 (0, 3.048)
  point P33 (-50.8, 237.8015)
  point P35 (-50.8, 237.8015)
  point P40 (-71.6837, 232.5587)
  point P53 (-50.8, 244.8458)
  coincident L3 P26
  perpendicular L3 L4
  coincident P33 P35
  coincident K19 P40
  coincident L6 P53
sketch "Sketch2" plane through (0, 0, 0) normal (0, 1, 0) x axis (1, 0, 0)
  line L1 (-95.6809, 124.1958) -> (-95.6809, 124.2212)
  line L2 (0, 266.7) -> (-50.8, 266.7)
  curve K1 (-58.9317, 239.3909) -> (-50.8, 244.8469)
  curve K2 (-50.8, 244.602) -> (-50.8, 244.8469)
  curve K3 (-50.904, 243.981) -> (-50.8, 244.602)
  curve K4 (-51.2936, 243.3317) -> (-50.904, 243.981)
  curve K5 (-51.734, 242.8041) -> (-51.2936, 243.3317)
  curve K6 (-53.328, 241.5518) -> (-51.734, 242.8041)
  curve K7 (-54.0892, 241.2477) -> (-53.328, 241.5518)
  curve K8 (-58.9317, 239.3909) -> (-54.0892, 241.2477)
  line L3 (-50.8, 266.7) -> (-50.8, 244.8458)
  curve K9 (-52.8501, 7.301) -> (-95.6809, 124.1958)
  curve K10 (-95.6814, 112.4293) -> (-95.6809, 124.1958)
  curve K11 (-95.1681, 95.3068) -> (-95.6814, 112.4293)
  curve K12 (-94.696, 81.2892) -> (-95.1681, 95.3068)
  curve K13 (-94.3798, 70.4902) -> (-94.696, 81.2892)
  curve K14 (-93.5014, 58.328) -> (-94.3798, 70.4902)
  curve K15 (-92.6826, 50.6119) -> (-93.5014, 58.328)
  curve K16 (-87.4432, 33.6688) -> (-92.6826, 50.6119)
  curve K17 (-83.6663, 27.4309) -> (-87.4432, 33.6688)
  curve K18 (-81.2455, 23.6666) -> (-83.6663, 27.4309)
  curve K19 (-79.8608, 22.0741) -> (-81.2455, 23.6666)
  curve K20 (-76.5846, 19.0457) -> (-79.8608, 22.0741)
  curve K21 (-73.7599, 16.6033) -> (-76.5846, 19.0457)
  curve K22 (-65.532, 11.7145) -> (-73.7599, 16.6033)
  curve K23 (-60.3553, 9.483) -> (-65.532, 11.7145)
  curve K24 (-55.4987, 7.9411) -> (-60.3553, 9.483)
  curve K25 (-54.6982, 7.6526) -> (-55.4987, 7.9411)
  curve K26 (-52.8501, 7.301) -> (-54.6982, 7.6526)
  line L4 (-95.6809, 124.2466) -> (-95.6809, 124.2212)
  line L5 (0, 3.048) -> (-6.35, 3.048)
  line L6 (-6.35, 3.048) -> (-14.1394, 3.048)
  curve K27 (-58.9317, 239.3909) -> (-95.6809, 124.2466)
  curve K28 (-95.6814, 136.0132) -> (-95.6809, 124.2466)
  curve K29 (-95.1681, 153.1357) -> (-95.6814, 136.0132)
  curve K30 (-94.696, 167.1533) -> (-95.1681, 153.1357)
  curve K31 (-94.3798, 177.9523) -> (-94.696, 167.1533)
  curve K32 (-93.5014, 190.1145) -> (-94.3798, 177.9523)
  curve K33 (-92.6826, 197.8306) -> (-93.5014, 190.1145)
  curve K34 (-87.4432, 214.7737) -> (-92.6826, 197.8306)
  curve K35 (-83.6663, 221.0115) -> (-87.4432, 214.7737)
  curve K36 (-81.2455, 224.7759) -> (-83.6663, 221.0115)
  curve K37 (-79.8608, 226.3684) -> (-81.2455, 224.7759)
  curve K38 (-76.5846, 229.3968) -> (-79.8608, 226.3684)
  curve K39 (-73.7599, 231.8391) -> (-76.5846, 229.3968)
  curve K40 (-65.833, 236.5491) -> (-73.7599, 231.8391)
  curve K41 (-61.4585, 238.4785) -> (-65.833, 236.5491)
  curve K42 (-58.9317, 239.3909) -> (-61.4585, 238.4785)
  line L7 (0, 3.048) -> (0, 266.7)
  arc A1 centre (-13.3279, 188.7329) radius 185.6867 clockwise from (-14.1394, 3.048) to (-52.8501, 7.301)
  point P52 (-50.8, 244.8458)
  coincident K1 P52
  perpendicular L5 L7
revolve "Revolve1" sketch "Sketch1" AlongAngle 360 bodies "Balon v3.3"
shell "Shell1" innerThickness 3.81
revolve "Revolve2" sketch "Sketch2" AlongAngle 360 bodies "Balon v3.2"
shell "Shell2" innerThickness 3.81
component_from_bodies "Body->Comp1"
component_from_bodies "Body->Comp2"
position "Position1"
remove_instance "RemoveInstance1" bodies "Balon v3"
remove_instance "RemoveInstance2"
move "Move1"
position "Position2" bodies "Balon v3"
sketch "Sketch3" plane through (0, 0, 0) normal (0, 1, 0) x axis (1, 0, 0)
  line L1 (0, 50.8) -> (0, -304.8)
  line L2 (127, 50.8) -> (127, -304.8)
  line L3 (-127, 50.8) -> (-127, -304.8)
  line L4 (139.7, 25.4) -> (-139.7, 25.4)
  line L5 (139.7, -292.1) -> (-139.7, -292.1)
  line L6 (95.25, 50.8) -> (95.25, -304.8)
  vertical L1
  dimension "d6" = 127
  dimension "d12" = -127
  dimension "d17" distance L4 L5 = 317.5
  dimension "d18" = 95.25
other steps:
base_feature "Base Feature1" bodies "Balon v3.3"
base_feature "Base Feature1" bodies "Balon v3.2"
base_feature "Base Feature1" bodies "Balon"
base_feature "Base Feature1" bodies "Balon v3"
base_feature "Base Feature1" bodies "Balon v2"
create_component "CreateComponent1"
remove_body "RemoveBody1"
create_component "CreateComponent2"
remove_body "RemoveBody2"
create_component "CreateComponent3"
remove_body "RemoveBody3" bodies "Balon v3"
create_component "CreateComponent1"
create_component "CreateComponent2"
remove_body "RemoveBody1" bodies "Balon v3"
create_component "CreateComponent3"
remove_body "RemoveBody2" bodies "Balon v3"
named bodies: "Balon", "Balon v2", "Balon v3", "Balon v3.3", "Balon v3.2"

design "Rubber Grommet"
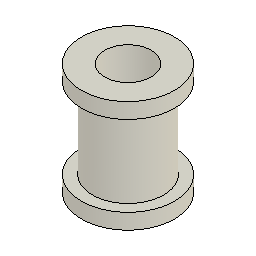
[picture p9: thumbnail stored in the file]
sketch "Sketch1" plane through (0, 0, 0) normal (0, 1, 0) x axis (1, 0, 0)
  line L1 (0, 3.048) -> (0, -12.7)
  line L2 (5.842, 0.508) -> (5.842, -12.7)
  line L3 (3.81, 3.048) -> (3.81, -15.24)
  line L4 (7.62, -12.7) -> (7.62, -15.24)
  line L5 (7.62, 3.048) -> (7.62, 0.508)
  line L6 (7.62, 0.508) -> (5.842, 0.508)
  line L7 (7.62, -12.7) -> (5.842, -12.7)
  line L8 (7.62, -15.24) -> (3.81, -15.24)
  line L9 (7.62, 3.048) -> (3.81, 3.048)
  vertical L1
  collinear L4 L5
revolve "Revolve1" sketch "Sketch1" AlongAngle 360 bodies "Rubber Grommet"
component_from_bodies "Body->Comp"
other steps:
base_feature "Base Feature" bodies "Rubber Grommet"
create_component "CreateComponent1"
remove_body "RemoveBody1"
named bodies: "Rubber Grommet"

design "Trove - TL"
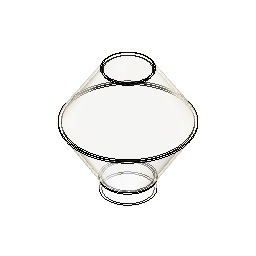
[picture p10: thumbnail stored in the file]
derived_base_feature "Derived Base Feature" bodies "Trove"
hole "Hole1" HoleDepth 88.9 HoleDiameter 44.45 TipAngle 118
sketch "Sketch1" plane through (0, 0, 0) normal (1, 0, 0) x axis (0, 1, 0)
  line L1 (0, 243.0601) -> (0, 247.8226)
  line L2 (-50.8, -12.7122) -> (-50.8, 10.9447)
  line L3 (0, -25.4) -> (0, 243.0601)
  line L4 (-46.0375, -12.7122) -> (-50.8, -12.7122)
  line L5 (-46.0375, -12.7122) -> (-46.0375, 12.3043)
  line L6 (-45.9716, 247.8226) -> (0, 247.8226)
  line L7 (-43.3841, 243.0601) -> (0, 243.0601)
  line L8 (-122.8321, 128.6352) -> (-51.757, 14.2971)
  line L9 (-117.1907, 128.5808) -> (-46.9945, 15.6567)
  line L10 (-48.6353, 246.3754) -> (-122.7993, 132.0392)
  line L11 (-46.0478, 241.6129) -> (-117.1579, 131.9848)
  arc A1 centre (-57.15, 10.9447) radius 6.35 clockwise from (-51.757, 14.2971) to (-50.8, 10.9447)
  arc A2 centre (-52.3875, 12.3043) radius 6.35 clockwise from (-46.9945, 15.6567) to (-46.0375, 12.3043)
  arc A3 centre (-114.4942, 130.257) radius 3.175 between (-117.1579, 131.9848) and (-117.1907, 128.5808)
  arc A4 centre (-120.1356, 130.3114) radius 3.175 between (-122.7993, 132.0392) and (-122.8321, 128.6352)
  arc A5 centre (-45.9716, 244.6476) radius 3.175 between (-45.9716, 247.8226) and (-48.6353, 246.3754)
  arc A6 centre (-43.3841, 239.8851) radius 3.175 clockwise from (-46.0478, 241.6129) to (-43.3841, 243.0601)
  point P3 (0, 247.8226)
  point P4 (0, 243.0601)
  vertical L1
  vertical L3
  tangent L5 A2
  perpendicular L1 L6
  perpendicular L1 L7
  tangent L11 A3
  tangent L9 A3
  tangent L10 A4
  tangent L8 A4
  equal A3 A4
  tangent L6 A5
  tangent L10 A5
  tangent L11 A6
  tangent L7 A6
  dimension "d8" distance P3 P4 = 4.7625
  dimension "d11" radius A2 = 6.35
  dimension "d15" radius A3 = 3.175
  dimension "d16" radius A5 = 3.175
  dimension "d17" radius A6 = 3.175
revolve "Revolve1" sketch "Sketch1" AlongAngle 180 bodies "Trove - TL"
revolve "Revolve2" sketch "Sketch1" AlongAngle -180
component_from_bodies "Body->Comp"
remove_body "RemoveBody2"
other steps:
base_feature "Base Feature" bodies "Trove - TL"
create_component "CreateComponent1"
remove_body "RemoveBody1"
named bodies: "Trove", "Trove - TL"

design "T9-5In"
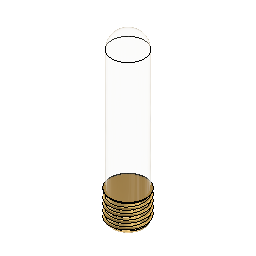
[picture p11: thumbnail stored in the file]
sketch "Sketch1" plane through (0, 0, 0) normal (0, 1, 0) x axis (1, 0, 0)
  line L1 (0, 0) -> (0, -127)
  line L2 (12.7, -127) -> (-12.7, -127)
  line L3 (12.7, -12.7) -> (12.7, -127)
  line L4 (-12.7, -127) -> (-12.7, -12.7)
  arc A1 centre (0, -12.7) radius 12.7 clockwise from (-12.7, -12.7) to (12.7, -12.7)
  point P1 (0, 0)
  point P3 (0, 0)
  coincident P1 P3
  vertical L1
  horizontal L2
  vertical L3
  vertical L4
revolve "Revolve1" sketch "Sketch1" AlongAngle 360 bodies "BU-T10-5-LED-120V"
derived_base_feature "Derived Base Feature" bodies "E26 Base"
move "Move1"
component_from_bodies "Body->Comp"
copy_paste "CutPaste"
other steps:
base_feature "Base Feature" bodies "BU-T10-5-LED-120V"
create_component "CreateComponent1"
create_component "CreateComponent2"
remove_body "RemoveBody1"
remove_instance "RemoveInstance1"
named bodies: "BU-T10-5-LED-120V", "E26 Base"
